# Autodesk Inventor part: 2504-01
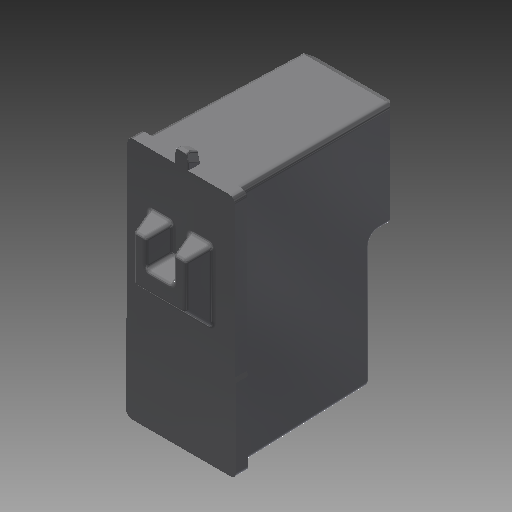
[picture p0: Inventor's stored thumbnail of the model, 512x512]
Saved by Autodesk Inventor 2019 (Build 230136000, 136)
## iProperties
Created: 2006-01
Part Number: 2504-01
Document SubType Name: Modeling
Designer: Autodesk Inc.
Density: 1.425 g/cm^3
Mass: 18.307 g
Surface Area: 182.523 cm^2
Volume: 12.847 cm^3
Material: Acetal Resin, Black
Appearance: Smooth - Medium Gray
Description: INK CARTRIDGE
MajorVersion: 11
MinorVersion: 1
Company: Autodesk Inc.
Author: Inventor
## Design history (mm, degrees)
sketch "Sketch1"
  geometry: L1 (12, -30)-(-12, -30); L2 (-12, -30)-(-12, 30); L3 (-12, 30)-(12, 30); L4 (12, 30)-(12, -30); L5 (-16.8, 0)-(16.8, 0) reference; L6 (0, 42)-(0, -42) reference
  constraints: 8 end point, 2 parallel, 1 horizontal, 1 perpendicular, 2 other
  dimensions: "d0" = 24 distance of L2.end L3.end; "d1" = 60 distance of L3.end L1.start
extrude "Extrusion1" new body sketch "Sketch1" distance "d2" = 40; taper "d3" = -1 deg
sketch "Sketch2"
  geometry: L1 (12, -30)-(-12, -30) reference; L2 (12, 30)-(12, -30) reference; L3 (-12, 30)-(12, 30) reference; L4 (-12, 30.5)-(12, 30.5); L5 (13.5, 29)-(13.5, -8.5); L6 (12.3, -30.5)-(-12.3, -30.5); L7 (-13.5, -8.5)-(-13.5, 29); L8 (-13.5, -8.5)-(-13.8, -9.5); L9 (-13.8, -9.5)-(-13.8, -29); L10 (13.8, -29)-(13.8, -9.5); L11 (13.8, -9.5)-(13.5, -8.5); L12 (0, 46.962)-(0, -43.773) reference; L13 (-19.755, 0)-(19.755, 0) reference; L14 (-1.75, 30.5)-(1.75, 30.5); L15 (1.75, 30.5)-(1.75, 34); L16 (1.75, 34)-(-1.75, 34); L17 (-1.75, 34)-(-1.75, 30.5); A1 r 1.5 centre (-12, 29) between (-12, 30.5) and (-13.5, 29); A2 r 1.5 centre (12, 29) between (13.5, 29) and (12, 30.5); A3 r 1.5 centre (12.3, -29) between (12.3, -30.5) and (13.8, -29); A4 r 1.5 centre (-12.3, -29) between (-13.8, -29) and (-12.3, -30.5); 4 further points
  constraints: 24 end point, 8 point on circle, 8 tangent, 7 point on line, 5 parallel, 4 centre point, 3 equal radius, 2 horizontal, 2 perpendicular, 2 symmetric about line, 3 other
  dimensions: "d4" = 0.5 distance between parallel lines of L3 L4; "d5" = 0.5 distance between parallel lines of L6 L1 (= d4); "d6" = 1.8 distance between parallel lines of L2 L10; "d7" = 1.5 distance between parallel lines of L2 L5; "d8" = 22 distance from line of L5.end L6; "d9" = 21 distance from line of L6 L10.end; "d12" = 1.5 radius of A1; "d15" = 3.5 distance of L15.end L16.end; "d16" = 3.5 distance of L14.end L15.end
extrude "Extrusion3" new body sketch "Sketch2" distance "d13" = 3; taper "d14" = 0 deg
chamfer "Chamfer1" distance "d17" = 2; stored, may be unused: second distance "d18" = 2, angle "d19" = 25 deg
chamfer "Chamfer2" distance "d20" = 2; stored, may be unused: second distance "d21" = 2, angle "d22" = 15 deg
chamfer "Chamfer3" distance "d23" = 2; stored, may be unused: second distance "d24" = 2, angle "d25" = 15 deg
sketch "Sketch4"
  geometry: L1 (-35.84, -40)-(3.302, -40); L2 (3.302, -40)-(3.302, -33); L3 (3.302, -33)-(-35.84, -33); L4 (-35.84, -33)-(-35.84, -40); L5 (-29.302, -40)-(29.302, -40) reference
  constraints: 8 end point, 2 parallel, 1 collinear, 1 horizontal, 1 perpendicular
  dimensions: "d40" = 26 distance from line of L2 L5.end; "d41" = 7 distance of L1.end L2.end
extrude "Extrusion5" cut sketch "Sketch4" extent not by distance; stored distance "d42" = 5.5; taper "d43" = 0 deg
sketch "Sketch5"
  geometry: L1 (22.848, -32.726)-(0, -32.726) reference; C1 r 3.5 at (11.424, -12.226); 1 further point
  constraints: 1 centre point, 1 midpoint, 1 vertical alignment
  dimensions: "d44" = 20.5 distance from line of L1 C1.centre; "d45" = 7 diameter of C1
extrude "Extrusion6" cut sketch "Sketch5" distance "d46" = 2; taper "d47" = -30 deg
sketch "Sketch6"
  geometry: L1 (-13.5, -8.5)-(-13.5, 29) reference; L2 (1.75, 30.5)-(12, 30.5) reference; L3 (-1.75, 30.5)-(1.75, 30.5); L4 (-11.3, 29.8)-(11.3, 29.8); L5 (12.8, 28.3)-(12.8, -28.3); L6 (11.3, -29.8)-(-11.3, -29.8); L7 (-12.8, -28.3)-(-12.8, 28.3); L8 (-11.5, 30)-(11.5, 30); L9 (13, 28.5)-(13, -28.5); L10 (11.5, -30)-(-11.5, -30); L11 (-13, -28.5)-(-13, 28.5); L12 (0, 46.9)-(0, -43.4) reference; L13 (-19.32, 0)-(19.32, 0) reference; A1 r 1.5 centre (-11.3, 28.3) between (-11.3, 29.8) and (-12.8, 28.3); A2 r 1.5 centre (11.3, 28.3) between (12.8, 28.3) and (11.3, 29.8); A3 r 1.5 centre (11.3, -28.3) between (11.3, -29.8) and (12.8, -28.3); A4 r 1.5 centre (-11.3, -28.3) between (-12.8, -28.3) and (-11.3, -29.8); A5 r 1.5 centre (-11.5, -28.5) between (-13, -28.5) and (-11.5, -30); A6 r 1.5 centre (11.5, -28.5) between (11.5, -30) and (13, -28.5); A7 r 1.5 centre (11.5, 28.5) between (13, 28.5) and (11.5, 30); A8 r 1.5 centre (-11.5, 28.5) between (-11.5, 30) and (-13, 28.5)
  constraints: 18 end point, 16 point on circle, 16 tangent, 8 centre point, 6 equal radius, 4 parallel, 2 horizontal, 2 perpendicular, 1 collinear, 2 other
  dimensions: "d48" = 1.5 radius of A1; "d49" = 1.5 radius of A5; "d50" = 0.2 distance between parallel lines of L8 L4; "d51" = 0.2 distance between parallel lines of L9 L5 (= d50); "d52" = 0.2 distance between parallel lines of L10 L6 (= d51); "d53" = 0.2 distance between parallel lines of L11 L7 (= d50); "d54" = 0.5 distance between parallel lines of L1 L11; "d55" = 0.5 distance between parallel lines of L2 L8
extrude "Extrusion7" cut sketch "Sketch6" distance "d56" = 0.2; taper "d57" = 0 deg
chamfer "Chamfer6" distance "d58" = 2; stored, may be unused: second distance "d59" = 2, angle "d60" = 60 deg
chamfer "Chamfer7" distance "d61" = 2; stored, may be unused: second distance "d62" = 2, angle "d63" = 30 deg
fillet "Fillet1" dims "d64" = 1.5
fillet "Fillet2" dims "d65" = 2
fillet "Fillet3" dims "d66" = 1
fillet "Fillet4" dims "d67" = 0.5
fillet "Fillet5" dims "d68" = 0.2
sketch "Sketch7"
  geometry: L1 (-9.302, 28.135)-(9.302, 28.135) reference; L2 (-9.302, 3.302)-(9.302, 3.302) reference; L3 (-7.25, 28.135)-(7.25, 28.135); L4 (7.25, 28.135)-(7.25, 3.302); L5 (7.25, 3.302)-(-7.25, 3.302); L6 (-7.25, 3.302)-(-7.25, 28.135); L7 (0, -42)-(0, 42) reference
  constraints: 8 end point, 2 parallel, 2 point on line, 1 horizontal, 1 perpendicular, 1 other
  dimensions: "d69" = 14.5 distance between parallel lines of L4 L6
extrude "Extrusion8" cut sketch "Sketch7" distance "d70" = 0.3; taper "d71" = 0 deg
sketch "Sketch12"
  geometry: L1 (-8, -0.639)-(8, -0.639); L2 (-8, -0.639)-(-8, 17.5); L3 (-8, 17.5)-(-2, 17.5); L4 (-2, 17.5)-(-2, 10.5); L5 (-2, 10.5)-(2, 10.5); L6 (2, 10.5)-(2, 17.5); L7 (2, 17.5)-(8, 17.5); L8 (8, 17.5)-(8, -0.639); L9 (11.5, -30)-(-11.5, -30) reference; L10 (13, 28.5)-(13, -28.5) reference
  constraints: 20 end point, 1 horizontal, 1 vertical
  dimensions: "d107" = 29.36066 distance between parallel lines of L9 L1; "d108" = 18.13934 distance of L7.end L1.end; "d109" = 16 distance of L1.start L1.end; "d110" = 5 distance between parallel lines of L10 L8; "d111" = 6 distance of L6.end L7.end; "d112" = 7 distance of L5.end L6.end; "d113" = 4 distance between parallel lines of L4 L6; "d114" = 6 distance of L2.end L3.end
extrude "Extrusion11" join sketch "Sketch12" distance "d78" = 5.5; taper "d79" = 0 deg
chamfer "Chamfer8" distance "d80" = 5.5; stored, may be unused: second distance "d81" = 2, angle "d82" = 45 deg
chamfer "Chamfer9" distance "d83" = 1.5; stored, may be unused: second distance "d84" = 5.5, angle "d85" = 45 deg
chamfer "Chamfer10" distance "d86" = 1.5; stored, may be unused: second distance "d87" = 5.5, angle "d88" = 45 deg
chamfer "Chamfer11" distance "d89" = 1.5; stored, may be unused: second distance "d90" = 5.5, angle "d91" = 45 deg
chamfer "Chamfer12" distance "d92" = 1.5; stored, may be unused: second distance "d93" = 5.5, angle "d94" = 45 deg
chamfer "Chamfer13" distance "d95" = 1.5; stored, may be unused: second distance "d96" = 5.5, angle "d97" = 45 deg
chamfer "Chamfer14" distance "d98" = 1.5; stored, may be unused: second distance "d99" = 5.5, angle "d100" = 45 deg
chamfer "Chamfer15" distance "d101" = 1.5; stored, may be unused: second distance "d102" = 5.5, angle "d103" = 45 deg
fillet "Fillet7" dims "d104" = 1
shell "Shell1" dims "d115" = 1
delete_face "Delete Face1"
sketch "Sketch13"
  geometry: L1 (7.25, 3.302)-(-7.25, 3.302) reference; L2 (7.25, 3.302)-(7.25, 28.135) reference; L3 (7.25, 28.135)-(-7.25, 28.135) reference; L4 (-7.25, 28.135)-(-7.25, 3.302) reference; L5 (-3.5, 14.135)-(3.5, 14.135); L6 (3.5, 14.135)-(3.5, 21.135); L7 (3.5, 21.135)-(-3.5, 21.135); L8 (-3.5, 21.135)-(-3.5, 14.135); L9 (0, 28.135)-(0, 3.302); L10 (-7.25, 15.718)-(7.25, 15.718); 1 further point
  constraints: 12 end point, 5 midpoint, 2 parallel, 2 perpendicular, 1 horizontal
  dimensions: "d116" = 7 distance of L6.end L7.end; "d117" = 7 distance of L7.end L5.start (= d116); "d118" = 3.5 distance between parallel lines of L8 L9 (= 0.5 x d116); "d123" = 7 distance between parallel lines of L7 L3
extrude "Extrusion12" cut sketch "Sketch13" extent not by distance; stored distance "d120" = 10; taper "d121" = 0 deg
fillet "Fillet8" dims "d122" = 1
body "Solid1"
body "Solid2"
node "Projected Loop1"
